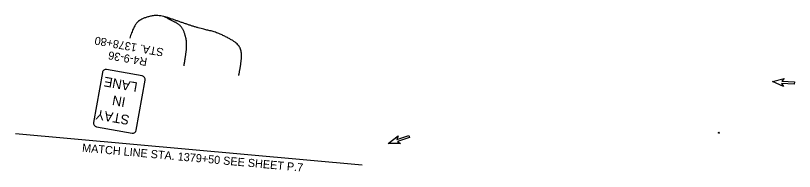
# Model space of a CAD drawing. Extents: x 217413 to 218294, y 612415 to 614235.
# Drawn here: x 217413 to 218084, y 613059 to 613193 of the extents above; entities that cross this region are included whole.
import ezdxf

# ---------------------------------------------------------------- set-up
doc = ezdxf.new("R2010")
doc.units = 0
for name, color, linetype in [('MT_P_Cells', 7, 'Continuous'), ('SH_Data', 7, 'Continuous'), ('SH_Masking', 7, 'Continuous'), ('SH_Text', 7, 'Continuous'), ('SN_P_Signs', 7, 'Continuous'), ('SN_P_Text', 7, 'Continuous')]:
    doc.layers.add(name, color=color, linetype=linetype)

msp = doc.modelspace()

# ---------------------------------------------------------------- linework, layer by layer
at = {"layer": 'MT_P_Cells'}
for p, q in [((218065.27, 613135.98), (218075.48, 613138.77)), ((218075.48, 613138.77), (218073.32, 613136.44)), ((218065.27, 613135.98), (218065.27, 613135.98)), ((218075.01, 613131.85), (218065.27, 613135.98)), ((218084.16, 613133.71), (218073.18, 613134.45)), ((218073.18, 613134.45), (218075.01, 613131.85)), ((218073.32, 613136.44), (218084.29, 613135.7)), ((218084.29, 613135.7), (218084.16, 613133.71)), ((218084.23, 613134.7), (218084.23, 613134.7)), ((217734.27, 613082.74), (217742.67, 613089.18)), ((217741.55, 613086.2), (217751.99, 613089.66)), ((217742.67, 613089.18), (217741.55, 613086.2)), ((217752.62, 613087.76), (217742.17, 613084.3)), ((217742.17, 613084.3), (217744.85, 613082.59)), ((217751.99, 613089.66), (217752.62, 613087.76)), ((217752.3, 613088.71), (217752.3, 613088.71)), ((217734.27, 613082.74), (217734.27, 613082.74)), ((217744.85, 613082.59), (217734.27, 613082.74))]:
    msp.add_line(p, q, dxfattribs=at)
at = {"layer": 'SH_Data'}
msp.add_line((217413.09, 613091.34), (217711.86, 613064.22), dxfattribs=at)
at = {"layer": 'SH_Masking'}
msp.add_circle((218019.24, 613091.93), 0.41, dxfattribs=at)
at = {"layer": 'SH_Text'}
for p, q in [((218019.24, 613092.31), (218018.93, 613091.97)), ((218018.93, 613091.97), (218019.54, 613091.97)), ((218019.54, 613091.97), (218019.24, 613092.31)), ((218019.24, 613091.97), (218019.24, 613091.58))]:
    msp.add_line(p, q, dxfattribs=at)
msp.add_circle((218019.24, 613091.93), 0.41, dxfattribs=at)
for points in [[(217605.42, 613141.25), (217607.31, 613150.29), (217608.19, 613161.88), (217604.26, 613169.5), (217586.01, 613178.83), (217571.52, 613181.72), (217553.92, 613187.77), (217535.89, 613193.97), (217522.3, 613190.58), (217515.5, 613185.34), (217511.44, 613173.52)], [(217558.27, 613149.64), (217559.55, 613157.47), (217560.72, 613166.58), (217560.08, 613173.77), (217556.7, 613183.23), (217549.16, 613188.12), (217541.93, 613191.47)]]:
    msp.add_open_spline(points, degree=2, dxfattribs=at)
at = {"layer": 'SN_P_Signs'}
for points in [[(217522.27, 613140.84), (217491.51, 613146.31)], [(217487.88, 613143.78), (217480.22, 613100.7)], [(217517.14, 613094.14), (217524.8, 613137.21)], [(217482.75, 613097.08), (217513.52, 613091.61)]]:
    msp.add_lwpolyline(points, dxfattribs=at)
for centre, radius, start, end in [((217490.96, 613143.23), 3.12, 79.91675, 169.91675), ((217521.73, 613137.76), 3.13, 349.91675, 79.91675), ((217483.3, 613100.16), 3.13, 169.91675, 259.91675), ((217514.07, 613094.69), 3.12, 259.91675, 349.91675)]:
    msp.add_arc(centre, radius, start, end, dxfattribs=at)

# ---------------------------------------------------------------- texts
at = {"layer": 'SH_Data'}
msp.add_text('MATCH LINE STA. 1379+50 SEE SHEET P.7', height=7, rotation=354.81337, dxfattribs=at).set_placement((217470.21, 613075.61))
at = {"layer": 'SH_Text'}
msp.add_text('N', height=0.25, dxfattribs=at).set_placement((218019.08, 613091.64))
at = {"layer": 'SN_P_Signs'}
for s, p in [('LANE', (217518.7, 613135.12)), ('IN', (217508.29, 613122.16)), ('STAY', (217511.75, 613106.74))]:
    msp.add_text(s, height=8.333, rotation=169.91675, dxfattribs=at).set_placement(p)
at = {"layer": 'SN_P_Text'}
for s, p in [('STA. 1378+80', (217541.13, 613164.4)), ('R4-9-36', (217526.98, 613156.25))]:
    msp.add_text(s, height=7, rotation=169.91675, dxfattribs=at).set_placement(p)

doc.saveas('drawing.dxf')
